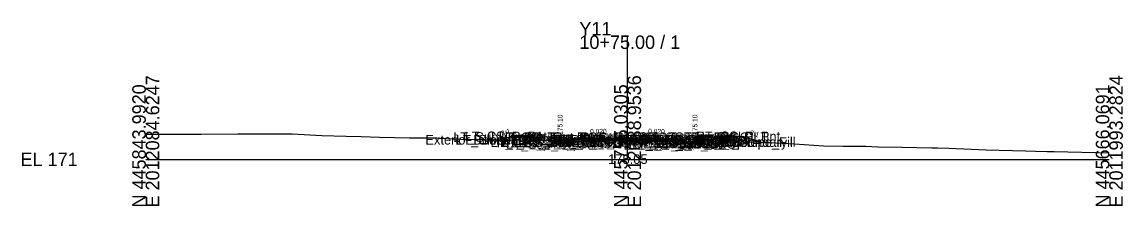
# Model space of a CAD drawing. Extents: x -26 to 203, y -10 to 3517.
# Drawn here: x -25.7 to 202.8, y 1490.3 to 1528.6 of the extents above; entities that cross this region are included whole.
import ezdxf

# ---------------------------------------------------------------- set-up
doc = ezdxf.new("R2010")
doc.units = 0
for name, color, linetype in [('Default', 7, 'Continuous'), ('Exist CMT Pavement', 7, 'Continuous'), ('Exist Cross Section Cell', 7, 'Continuous'), ('Exist XS Center Line Elevation Label', 7, 'Continuous'), ('Exist XS Ground Line', 7, 'Continuous'), ('Prop CMT Conc Surface', 7, 'Continuous'), ('Prop CMT Concrete Structures', 7, 'Continuous'), ('Prop CMT Pvmt Course 1', 7, 'Continuous'), ('Prop CMT Pvmt Course 1 CG', 7, 'Continuous'), ('Prop CMT Pvmt Course 1 Wedge', 7, 'Continuous'), ('Prop CMT Pvmt Course 2', 7, 'Continuous'), ('Prop CMT Pvmt Course 2 Wedge', 7, 'Continuous'), ('Prop CMT Pvmt Course 3', 7, 'Continuous'), ('Prop CMT Pvmt Course 3 Wedge', 7, 'Continuous'), ('Prop CMT Pvmt Surface', 7, 'Continuous'), ('Prop CMT Pvmt Wedge Surface 1', 7, 'Continuous'), ('Prop CMT Pvmt Wedge Surface 2', 7, 'Continuous'), ('Prop CMT Pvmt Wedge Surface 3', 7, 'Continuous'), ('Prop CMT Slope Grass', 7, 'Continuous'), ('Prop CMT Subgrade Earthwork', 7, 'Continuous'), ('Prop XS Earthwork Shape', 7, 'Continuous'), ('Prop XS Hydro Elevations', 7, 'Continuous'), ('Prop XS SE Text', 7, 'Continuous'), ('Prop XS Side Slope Text', 7, 'Continuous'), ('Scratch_Level_0', 7, 'Continuous')]:
    doc.layers.add(name, color=color, linetype=linetype)

msp = doc.modelspace()

# ---------------------------------------------------------------- linework, layer by layer
at = {"layer": 'Exist CMT Pavement'}
msp.add_line((100, 1504.05), (89.01, 1503.65), dxfattribs=at)
msp.add_lwpolyline([(100, 1504.05), (111, 1503.61)], dxfattribs=at)
at = {"layer": 'Exist Cross Section Cell'}
for p, q in [((100, 1500), (100, 1525.76)), ((0, 1500), (100, 1500)), ((100, 1500), (200, 1500))]:
    msp.add_line(p, q, dxfattribs=at)
at = {"layer": 'Exist XS Ground Line'}
msp.add_lwpolyline([(0, 1505.27), (5.6, 1505.27), (11.46, 1505.21), (19.1, 1505.33), (27.27, 1505.34), (27.68, 1505.33), (28.64, 1505.32), (30.36, 1505.29), (36.54, 1504.95), (41.59, 1504.81), (44.68, 1504.76), (48.49, 1504.63), (54.72, 1504.5), (56.49, 1504.45), (60.47, 1504.47), (60.96, 1504.43), (65.42, 1504.17), (80.73, 1504.02), (85.66, 1503.93), (87.27, 1503.83), (88.82, 1503.64), (99.65, 1504.04), (100.01, 1504.05), (111.94, 1503.58), (113.25, 1503.73), (127.21, 1503.6), (129.44, 1503.54), (134.64, 1503.22), (140.68, 1502.8), (144.76, 1502.73), (149.49, 1502.75), (151.93, 1502.64), (156.92, 1502.52), (163.17, 1502.41), (164.35, 1502.37), (166.66, 1502.3), (174.41, 1501.97), (182.59, 1501.81), (184.65, 1501.74), (187.08, 1501.66), (188.56, 1501.63), (200, 1501.38)], dxfattribs=at)
at = {"layer": 'Prop CMT Conc Surface'}
for points in [[(86, 1504.1), (86, 1504.6), (85.5, 1504.6)], [(88, 1504.22), (86, 1504.1)], [(112, 1504.22), (114, 1504.1)], [(114, 1504.1), (114, 1504.6), (114.5, 1504.6)]]:
    msp.add_lwpolyline(points, dxfattribs=at)
at = {"layer": 'Prop CMT Concrete Structures'}
for points in [[(88, 1504.22), (86, 1504.1), (86, 1504.6), (85.5, 1504.6)], [(85.5, 1504.6), (85.5, 1503.58), (88, 1503.63)], [(88, 1503.63), (88, 1504.22)], [(112, 1504.22), (114, 1504.1), (114, 1504.6), (114.5, 1504.6)], [(114.5, 1504.6), (114.5, 1503.58), (112, 1503.63)], [(112, 1503.63), (112, 1504.22)]]:
    msp.add_lwpolyline(points, dxfattribs=at)
at = {"layer": 'Prop CMT Pvmt Course 1'}
for points in [[(100, 1504.46), (88, 1504.22)], [(88, 1504.22), (88, 1503.97)], [(88, 1503.97), (89, 1503.99)], [(89, 1504.11), (100, 1504.33)], [(89, 1503.99), (89, 1504.11)], [(100, 1504.21), (100, 1504.46)], [(100, 1504.46), (112, 1504.22)], [(100, 1504.21), (100, 1504.46)], [(100, 1504.33), (100, 1504.21), (100, 1504.21)], [(111, 1504.11), (100, 1504.33)], [(100, 1504.33), (100, 1504.21), (100, 1504.21)], [(111, 1503.99), (111, 1504.11)], [(112, 1503.97), (111, 1503.99)], [(112, 1504.22), (112, 1503.97)]]:
    msp.add_lwpolyline(points, dxfattribs=at)
at = {"layer": 'Prop CMT Pvmt Course 1 CG'}
for points in [[(88, 1503.63), (85, 1503.57), (84.66, 1503.23)], [(84.66, 1503.23), (88, 1503.3)], [(88, 1503.3), (88, 1503.63)], [(112, 1503.63), (115, 1503.57), (115.34, 1503.23)], [(112, 1503.3), (112, 1503.63)], [(115.34, 1503.23), (112, 1503.3)]]:
    msp.add_lwpolyline(points, dxfattribs=at)
at = {"layer": 'Prop CMT Pvmt Course 1 Wedge'}
for points in [[(100, 1504.33), (89, 1504.11)], [(100, 1504.33), (111, 1504.11)]]:
    msp.add_lwpolyline(points, dxfattribs=at)
at = {"layer": 'Prop CMT Pvmt Course 2'}
for points in [[(89, 1503.99), (88, 1503.97)], [(88, 1503.97), (88, 1503.63)], [(89, 1503.65), (89, 1503.99)], [(111, 1503.65), (111, 1503.99)], [(111, 1503.99), (112, 1503.97)], [(112, 1503.97), (112, 1503.63)], [(88, 1503.63), (89, 1503.65)], [(112, 1503.63), (111, 1503.65)]]:
    msp.add_lwpolyline(points, dxfattribs=at)
at = {"layer": 'Prop CMT Pvmt Course 2 Wedge'}
for points in [[(100, 1504.21), (89, 1503.99)], [(100, 1504.21), (89, 1503.99)], [(100, 1504.21), (111, 1503.99)], [(100, 1504.21), (111, 1503.99)]]:
    msp.add_lwpolyline(points, dxfattribs=at)
at = {"layer": 'Prop CMT Pvmt Course 3'}
for points in [[(89, 1503.65), (88, 1503.63)], [(88, 1503.63), (88, 1503.3)], [(88, 1503.3), (89, 1503.32)], [(89, 1503.32), (89, 1503.65)], [(111, 1503.65), (112, 1503.63)], [(111, 1503.32), (111, 1503.65)], [(112, 1503.3), (111, 1503.32)], [(112, 1503.63), (112, 1503.3)]]:
    msp.add_lwpolyline(points, dxfattribs=at)
at = {"layer": 'Prop CMT Pvmt Course 3 Wedge'}
for points in [[(100, 1503.87), (89, 1503.65)], [(100, 1503.87), (111, 1503.65)]]:
    msp.add_lwpolyline(points, dxfattribs=at)
at = {"layer": 'Prop CMT Pvmt Surface'}
for points in [[(100, 1504.46), (88, 1504.22)], [(100, 1504.46), (112, 1504.22)]]:
    msp.add_lwpolyline(points, dxfattribs=at)
at = {"layer": 'Prop CMT Pvmt Wedge Surface 1'}
for points in [[(88, 1503.97), (88, 1504.22)], [(89, 1503.99), (88, 1503.97)], [(100, 1504.33), (89, 1504.11)], [(89, 1504.11), (89, 1503.99)], [(100, 1504.33), (111, 1504.11)], [(111, 1504.11), (111, 1503.99)], [(111, 1503.99), (112, 1503.97)], [(112, 1503.97), (112, 1504.22)]]:
    msp.add_lwpolyline(points, dxfattribs=at)
at = {"layer": 'Prop CMT Pvmt Wedge Surface 2'}
for points in [[(88, 1503.97), (88, 1504.22)], [(100, 1504.21), (88, 1503.97)], [(100, 1504.21), (112, 1503.97)], [(112, 1503.97), (112, 1504.22)]]:
    msp.add_lwpolyline(points, dxfattribs=at)
at = {"layer": 'Prop CMT Pvmt Wedge Surface 3'}
for points in [[(88, 1503.63), (88, 1504.22)], [(100, 1503.87), (88, 1503.63)], [(100, 1503.87), (112, 1503.63)], [(112, 1503.63), (112, 1504.22)]]:
    msp.add_lwpolyline(points, dxfattribs=at)
at = {"layer": 'Prop CMT Slope Grass'}
for points in [[(85.5, 1504.6), (76, 1504.79), (73.89, 1504.08)], [(114.5, 1504.6), (124, 1504.79), (127.6, 1503.59)]]:
    msp.add_lwpolyline(points, dxfattribs=at)
at = {"layer": 'Prop CMT Subgrade Earthwork'}
for points in [[(88, 1503.3), (84.66, 1503.23), (83.25, 1504.64)], [(112, 1503.3), (115.34, 1503.23), (116.75, 1504.64)], [(89, 1503.32), (88, 1503.3)], [(89, 1503.32), (89.01, 1503.65)], [(111, 1503.32), (110.98, 1503.61)], [(111, 1503.32), (112, 1503.3)]]:
    msp.add_lwpolyline(points, dxfattribs=at)
at = {"layer": 'Prop XS Earthwork Shape'}
for points in [[(83.93, 1503.96), (83.25, 1504.64), (76, 1504.79), (73.89, 1504.08), (80.73, 1504.02)], [(83.93, 1503.96), (85.5, 1503.93), (85.5, 1503.58), (88, 1503.63), (88, 1503.74), (88.82, 1503.64), (89.01, 1503.65), (89, 1503.32), (88, 1503.3), (84.66, 1503.23)], [(88, 1503.63), (88, 1503.74), (87.27, 1503.83), (85.66, 1503.93), (85.5, 1503.93), (85.5, 1503.58)], [(89.01, 1503.65), (99.65, 1504.04), (100, 1504.05)], [(115.81, 1503.71), (127.21, 1503.6), (127.6, 1503.59), (124, 1504.79), (116.75, 1504.64)], [(111, 1503.32), (112, 1503.3), (115.34, 1503.23), (115.81, 1503.71), (114.5, 1503.72), (114.5, 1503.58), (112.36, 1503.63), (111.94, 1503.58), (111, 1503.61), (110.98, 1503.61)], [(114.5, 1503.72), (114.5, 1503.58), (112.36, 1503.63), (113.25, 1503.73)]]:
    msp.add_lwpolyline(points, close=True, dxfattribs=at)

# ---------------------------------------------------------------- texts
at = {"layer": 'Default'}
msp.add_text('-', height=0.0001, dxfattribs=at).set_placement((0, 1500))
at = {"layer": 'Exist Cross Section Cell'}
for s, p in [('Y11', (90, 1525.76)), ('10+75.00 / 1', (90, 1522.96)), ('EL 171', (-26, 1498.6))]:
    msp.add_text(s, height=2.8, dxfattribs=at).set_placement(p)
for s, p in [('N 445843.9920', (0, 1490)), ('E 2012084.6247', (2.8, 1490)), ('N 445755.0305', (100, 1490)), ('E 2012038.9536', (102.8, 1490)), ('N 445666.0691', (200, 1490)), ('E 2011993.2824', (202.8, 1490))]:
    msp.add_text(s, height=2.8, rotation=90, dxfattribs=at).set_placement(p)
at = {"layer": 'Exist XS Center Line Elevation Label'}
msp.add_text('175.05', height=2, dxfattribs=at).set_placement((95.98, 1499.05))
at = {"layer": 'Prop XS Hydro Elevations'}
for p in [(86.5, 1505.1), (114.5, 1505.1)]:
    msp.add_text('175.10', height=1, rotation=90, dxfattribs=at).set_placement(p)
at = {"layer": 'Prop XS SE Text'}
for rotation, p in [(1.1458, (92.23, 1505.3)), (358.8542, (104.27, 1505.37))]:
    msp.add_text('0.020', height=1, rotation=rotation, dxfattribs=at).set_placement(p)
at = {"layer": 'Prop XS Side Slope Text'}
for rotation, p in [(18.4332, (73.95, 1504.9)), (341.5668, (125.29, 1505.15))]:
    msp.add_text('3:1', height=1, rotation=rotation, dxfattribs=at).set_placement(p)
at = {"layer": 'Scratch_Level_0'}
for s, p in [('Exterior Boundary', (58.03, 1503.08)), ('LT_Sub_Trench_Out_DLT', (63.82, 1503.64)), ('LT_Slope_Fill', (64.4, 1503.08)), ('LT_CSLP_Pnt', (66.17, 1503.79)), ('LT_CG1_Shelf_Out', (71.55, 1502.57)), ('LT_CG_Top_Face', (73.26, 1503.6)), ('LT_CG_Top_BOC', (73.78, 1503.6)), ('LT_CG_Bot_BOC', (73.81, 1502.58)), ('LT_PV_Sub_Tie_Out', (73.96, 1502.65)), ('LT_CG_Top_Gut', (74.24, 1503.1)), ('LT_Sub_OEOP', (74.77, 1502.23)), ('LT_PV_OEEOP_EG', (76.54, 1502.65)), ('LT_CG_Bot_IE', (77.91, 1502.63)), ('LT_Sub_OEOT', (78.08, 1502.3)), ('LT_PV2_OEOT', (78.17, 1502.97)), ('LT_PV3_OEOT', (78.17, 1502.63)), ('LT_Sub_OEEOP', (78.21, 1502.32)), ('LT_PV2_OEEOP', (78.31, 1502.99)), ('LT_PV3_OEEOP', (78.31, 1502.65)), ('LT_PV1_OEOT', (78.74, 1503.22)), ('LT_PV1_OEEOP', (78.87, 1503.11)), ('RT_PV_IEEOP_EG', (88.14, 1503.05)), ('LT_PV_IEEOP_EG', (88.19, 1503.05)), ('RT_PV2_IEEOP', (89.91, 1503.21)), ('RT_PV3_IEEOP', (89.91, 1502.87)), ('LT_PV2_IEEOP', (89.95, 1503.21)), ('LT_PV3_IEEOP', (89.95, 1502.87)), ('RT_PV1_IEEOP', (90.47, 1503.33)), ('LT_PV1_IEEOP', (90.52, 1503.33)), ('PV2_PGL', (93.91, 1503.21)), ('PV1_PGL', (94.47, 1503.46)), ('RT_PV_Sub_Tie_Out', (95.88, 1502.61)), ('RT_Sub_Trench_Out_DLT', (97.27, 1503.64)), ('RT_PV_OEEOP_EG', (98.5, 1502.61)), ('RT_Sub_OEEOP', (100.17, 1502.32)), ('RT_PV2_OEEOP', (100.26, 1502.99)), ('RT_PV3_OEEOP', (100.26, 1502.65)), ('RT_PV1_OEEOP', (100.83, 1503.11)), ('RT_CG_Top_Face', (101.21, 1503.6)), ('RT_CG1_Shelf_Out', (101.5, 1502.57)), ('RT_CG_Bot_IE', (101.87, 1502.63)), ('RT_Sub_OEOT', (102.03, 1502.3)), ('RT_PV2_OEOT', (102.13, 1502.97)), ('RT_PV3_OEOT', (102.13, 1502.63)), ('RT_CG_Top_Gut', (102.19, 1503.1)), ('RT_PV1_OEOT', (102.69, 1503.22)), ('RT_CG_Top_BOC', (102.74, 1503.6)), ('RT_CG_Bot_BOC', (102.77, 1502.58)), ('RT_Sub_OEOP', (105.4, 1502.23)), ('Exterior Boundary', (111.74, 1502.59)), ('RT_CSLP_Pnt', (114.13, 1503.79)), ('RT_Slope_Fill', (118.08, 1502.59))]:
    msp.add_text(s, height=2, dxfattribs=at).set_placement(p)

doc.saveas('drawing.dxf')
